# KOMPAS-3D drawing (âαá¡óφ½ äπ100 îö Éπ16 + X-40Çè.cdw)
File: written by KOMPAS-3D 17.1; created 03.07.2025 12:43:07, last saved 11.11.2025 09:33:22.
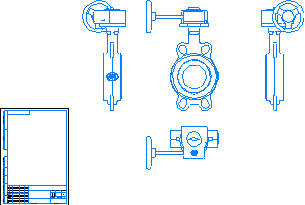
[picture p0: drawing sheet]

Sheet 1: A4, portrait

Title block, sheet 1: sheets: 1; sheet format: A4; stored path: \\adlc.lan\data\АДЛ_ПКД\3D-модели\ADL production\Дисковые поворотные затворы ГРАНВЭЛ\межфланцевый с китайским редуктором Ру16\KOMPAS 2D\Гранвэл Ду100 МФ Ру16 + X-40АК.cdw

Views: Вид 1, Спереди, Проекционный вид 2, Проекционный вид 3, Проекционный вид 4
Referenced files in \\adlc.lan\data\АДЛ_ПКД\3D-модели\ADL production\Дисковые поворотные затворы ГРАНВЭЛ\межфланцевый с китайским редуктором Ру16\KOMPAS 3D\: Гранвэл Ду100 МФ Ру16 + X-40АК.m3d
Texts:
  Andrey
  АДЛ
Dimensions and other numbers on the sheet: 1:1; 1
